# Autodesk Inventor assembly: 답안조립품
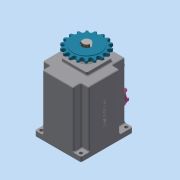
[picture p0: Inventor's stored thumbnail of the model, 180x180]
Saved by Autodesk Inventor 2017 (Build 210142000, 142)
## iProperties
Part Number: 답안조립품
Material: 일반
Document SubType Name: Assembly
Designer: MRC
Author: MRC
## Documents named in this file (16)
- C:\Users\MRC\Desktop\720212V1002\답안조립품.iam
- C:\Users\MRC\Desktop\720212V1002\본체.ipt
- C:\Users\MRC\Desktop\720212V1002\멈춤나사 M3.ipt
- C:\Users\MRC\Desktop\720212V1002\메인 축.ipt
- C:\Users\MRC\Desktop\720212V1002\베어링 608.ipt
- C:\Users\MRC\Desktop\720212V1002\베어링 6003.ipt
- C:\Users\MRC\Desktop\720212V1002\볼트 M4 x 10.ipt
- C:\Users\MRC\Desktop\720212V1002\부시.ipt
- C:\Users\MRC\Desktop\720212V1002\상부 캡.ipt
- C:\Users\MRC\Desktop\720212V1002\서브 축.ipt
- C:\Users\MRC\Desktop\720212V1002\스프로킷.ipt
- C:\Users\MRC\Desktop\720212V1002\슬라이더.ipt
- C:\Users\MRC\Desktop\720212V1002\오일 실 8 x 22 x 7.ipt
- C:\Users\MRC\Desktop\720212V1002\오일 실 17 x 32 x 8.ipt
- C:\Users\MRC\Desktop\720212V1002\커버.ipt
- C:\Users\MRC\Desktop\720212V1002\키 5 x 5.ipt
